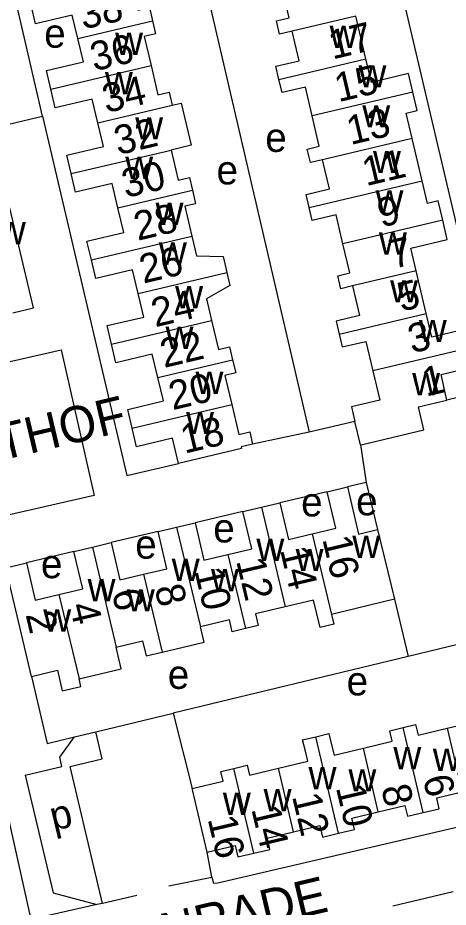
# Model space of a CAD drawing. Extents: x 157646 to 159241, y 379213 to 381217.
# Drawn here: x 158907.8 to 158967.4, y 380734 to 380857.1 of the extents above; entities that cross this region are included whole.
import ezdxf

# ---------------------------------------------------------------- set-up
doc = ezdxf.new("R2010")
doc.units = 0
for name, color, linetype in [('BLT_Basislijn', 7, 'Continuous'), ('BLT_Bebouwing', 7, 'Continuous'), ('BLT_Centroide', 7, 'Continuous'), ('BLT_Huisnummer', 7, 'Continuous'), ('BLT_Huisnummer_ tussenligend', 7, 'Continuous'), ('BLT_Onderverdeling_panden', 7, 'Continuous'), ('BLT_Straatnaam', 7, 'Continuous')]:
    doc.layers.add(name, color=color, linetype=linetype)

msp = doc.modelspace()

# ---------------------------------------------------------------- linework, layer by layer
at = {"layer": 'BLT_Basislijn'}
for p, q in [((158903.89, 380841.72), (158911.21, 380843.45)), ((158973.83, 380805.75), (158967.23, 380804.14)), ((158954.48, 380801.16), (158948.14, 380799.71)), ((158955.27, 380797.94), (158954.48, 380801.16)), ((158948.14, 380799.71), (158940.31, 380798.06)), ((158955.27, 380797.94), (158956.05, 380792.74)), ((158956.05, 380792.74), (158953.46, 380792.12)), ((158950.64, 380791.45), (158944.09, 380789.93)), ((158938.97, 380788.72), (158932.35, 380787.16)), ((158927.22, 380785.95), (158920.74, 380784.41)), ((158915.56, 380783.18), (158908.99, 380781.61)), ((158972.42, 380771.22), (158961.87, 380768.65)), ((158961.87, 380768.65), (158929.32, 380760.8)), ((158909.72, 380765.9), (158911.89, 380756.62)), ((158918.59, 380758.23), (158929.32, 380760.8)), ((158929.32, 380760.8), (158931.95, 380750.4)), ((158911.89, 380756.62), (158915.65, 380757.53)), ((158913.61, 380754.71), (158915.65, 380757.53)), ((158915.65, 380757.53), (158918.59, 380758.23)), ((158919.48, 380754.47), (158918.59, 380758.23)), ((158904.57, 380754.81), (158909.61, 380732.25)), ((158913.92, 380753.43), (158913.61, 380754.71)), ((158915.04, 380753.42), (158919.48, 380754.47)), ((158908.83, 380752.22), (158913.92, 380753.43)), ((158919.54, 380734.49), (158915.04, 380753.42)), ((158908.83, 380752.22), (158912.7, 380735.95)), ((158934.65, 380738.13), (158934.04, 380741.58)), ((158928.73, 380736.91), (158934.65, 380738.13)), ((158912.7, 380735.95), (158918.73, 380734.31)), ((158924.29, 380735.57), (158919.54, 380734.49)), ((158968.1, 380736.07), (158959.72, 380734.11)), ((158918.73, 380734.31), (158909.61, 380732.25)), ((158919.54, 380734.49), (158918.73, 380734.31))]:
    msp.add_line(p, q, dxfattribs=at)
for points in [[(158950.45, 380874.83), (158953.9, 380875.15), (158955.51, 380874.99), (158957.69, 380873.05), (158958.48, 380871.06), (158973.83, 380805.75)], [(158931.91, 380870.58), (158932.87, 380865.39), (158948.14, 380799.71)], [(158911.21, 380843.45), (158907.1, 380861.22), (158906.52, 380864.85)], [(158911.21, 380843.45), (158922.91, 380793.71), (158930.05, 380795.37)], [(158897.4, 380807.37), (158913.83, 380811.08), (158918.39, 380790.92), (158901.96, 380787.2), (158897.4, 380807.37)], [(158956.05, 380792.74), (158957.62, 380786.24)], [(158959.95, 380776.58), (158961.87, 380768.65)], [(158934.65, 380738.13), (158934.9, 380737.3), (158935.48, 380737.32), (158983.21, 380748.46), (158985.53, 380750.59), (158985.91, 380751.64), (158986.02, 380754.38), (158982.31, 380770.52)]]:
    msp.add_lwpolyline(points, dxfattribs=at)
at = {"layer": 'BLT_Bebouwing'}
for p, q in [((158955.99, 380851.35), (158954.6, 380857.26)), ((158963.78, 380834.49), (158962.42, 380840.34)), ((158964.36, 380816.13), (158962.97, 380822.02)), ((158950.64, 380791.45), (158953.46, 380792.12)), ((158938.97, 380788.72), (158941.53, 380789.33)), ((158941.53, 380789.33), (158944.09, 380789.93)), ((158929.79, 380786.55), (158932.35, 380787.16)), ((158927.22, 380785.95), (158929.79, 380786.55)), ((158918.15, 380783.79), (158920.74, 380784.41)), ((158915.56, 380783.18), (158918.15, 380783.79))]:
    msp.add_line(p, q, dxfattribs=at)
for points in [[(158923.49, 380862.09), (158924.44, 380858.1), (158926.04, 380858.48), (158926.47, 380856.64)], [(158945.8, 380855.18), (158944.05, 380854.77), (158943.61, 380856.64), (158945.38, 380857.05), (158944.49, 380860.81)], [(158916.11, 380854.19), (158915.35, 380857.42), (158910.25, 380856.22), (158909.64, 380858.81)], [(158926.47, 380856.64), (158926.89, 380854.85), (158925.3, 380854.47), (158926.25, 380850.44)], [(158943.96, 380848.52), (158943.53, 380850.35), (158946.77, 380851.11), (158945.8, 380855.18)], [(158912.38, 380847.16), (158911.77, 380849.76), (158916.88, 380850.97), (158916.11, 380854.19)], [(158962.48, 380846.77), (158961.88, 380849.32), (158956.76, 380848.11), (158955.99, 380851.35)], [(158926.25, 380850.44), (158927.2, 380846.4), (158928.77, 380846.77), (158929.2, 380844.94)], [(158948.56, 380843.49), (158947.62, 380847.45), (158944.4, 380846.69), (158943.96, 380848.52)], [(158918.89, 380842.5), (158918.12, 380845.78), (158913, 380844.57), (158912.38, 380847.16)], [(158962.42, 380840.34), (158961.59, 380843.87), (158963.08, 380844.22), (158962.48, 380846.77)], [(158929.2, 380844.94), (158930.42, 380845.23), (158931.8, 380839.41), (158929.04, 380838.75)], [(158950, 380837.41), (158948.31, 380837.01), (158947.87, 380838.89), (158949.55, 380839.29), (158948.56, 380843.49)], [(158915.2, 380835.48), (158914.6, 380838.03), (158919.66, 380839.23), (158918.89, 380842.5)], [(158929.04, 380838.75), (158930.02, 380834.59), (158931.57, 380834.96), (158931.99, 380833.18)], [(158948.14, 380830.8), (158947.71, 380832.61), (158950.96, 380833.37), (158950, 380837.41)], [(158921.67, 380830.73), (158920.87, 380834.12), (158915.81, 380832.93), (158915.2, 380835.48)], [(158966.64, 380829.03), (158966.01, 380831.7), (158964.52, 380831.35), (158963.78, 380834.49)], [(158931.99, 380833.18), (158932.43, 380831.32), (158930.91, 380830.97), (158931.89, 380826.83)], [(158907.14, 380816.24), (158909.97, 380816.9), (158906.71, 380830.73)], [(158917.99, 380823.55), (158917.38, 380826.14), (158922.47, 380827.35), (158921.67, 380830.73)], [(158952.81, 380825.77), (158951.87, 380829.77), (158948.57, 380828.99), (158948.14, 380830.8)], [(158962.97, 380822.02), (158962.23, 380825.18), (158967.27, 380826.36), (158966.64, 380829.03)], [(158931.89, 380826.83), (158932.54, 380824.09), (158936.24, 380824.03), (158936.76, 380821.82)], [(158954.16, 380819.94), (158952.53, 380819.56), (158952.1, 380821.36), (158953.76, 380821.75), (158952.81, 380825.77)], [(158924.46, 380818.9), (158923.69, 380822.16), (158918.61, 380820.95), (158917.99, 380823.55)], [(158936.76, 380821.82), (158937.18, 380820.02), (158933.93, 380818.14), (158934.64, 380815.16)], [(158920.8, 380811.88), (158920.19, 380814.45), (158925.24, 380815.64), (158924.46, 380818.9)], [(158954.16, 380819.94), (158955.13, 380815.84), (158951.88, 380815.08), (158952.3, 380813.28)], [(158934.64, 380815.16), (158935.58, 380811.15), (158937.13, 380811.51), (158937.55, 380809.71)], [(158970.81, 380811.46), (158970.2, 380814.05), (158965.13, 380812.86), (158964.36, 380816.13)], [(158952.3, 380813.28), (158952.72, 380811.49), (158955.99, 380812.26), (158956.95, 380808.19)], [(158927.2, 380807.26), (158926.43, 380810.51), (158921.4, 380809.32), (158920.8, 380811.88)], [(158967.23, 380804.14), (158966.4, 380807.68), (158971.42, 380808.86), (158970.81, 380811.46)], [(158937.55, 380809.71), (158937.98, 380807.9), (158936.48, 380807.55), (158937.43, 380803.52)], [(158956.95, 380808.19), (158957.92, 380804.11), (158954.01, 380803.19), (158954.48, 380801.16)], [(158923.64, 380800.26), (158923.02, 380802.85), (158927.96, 380804.02), (158927.2, 380807.26)], [(158955.27, 380797.94), (158955.54, 380798.01), (158964.03, 380800.01), (158963.28, 380803.21), (158967.23, 380804.14)], [(158937.43, 380803.52), (158938.41, 380799.37), (158939.92, 380799.73), (158940.31, 380798.06)], [(158930.05, 380795.37), (158929.23, 380798.85), (158924.25, 380797.68), (158923.64, 380800.26)], [(158940.31, 380798.06), (158938.71, 380797.68), (158938.77, 380797.44), (158930.05, 380795.37)], [(158953.46, 380792.12), (158955, 380785.6), (158957.62, 380786.24)], [(158948.56, 380785.65), (158951.83, 380786.42), (158950.64, 380791.45)], [(158944.09, 380789.93), (158945.29, 380784.87), (158948.56, 380785.65)], [(158936.88, 380782.79), (158940.19, 380783.57), (158938.97, 380788.72)], [(158932.35, 380787.16), (158933.57, 380782.01), (158936.88, 380782.79)], [(158925.2, 380780.04), (158928.44, 380780.81), (158927.22, 380785.95)], [(158957.62, 380786.24), (158959.95, 380776.58)], [(158920.74, 380784.41), (158921.95, 380779.27), (158925.2, 380780.04)], [(158913.5, 380777.22), (158916.79, 380778), (158915.56, 380783.18)], [(158909.72, 380765.9), (158906.16, 380780.93), (158908.99, 380781.61)], [(158908.99, 380781.61), (158910.21, 380776.44), (158913.5, 380777.22)], [(158951.24, 380774.49), (158951.57, 380773.12), (158949.66, 380772.66), (158948.75, 380776.47), (158944.84, 380775.54)], [(158959.95, 380776.58), (158951.24, 380774.49)], [(158944.84, 380775.54), (158940.7, 380774.56), (158941.08, 380772.93), (158939.31, 380772.52)], [(158939.31, 380772.52), (158937.49, 380772.08), (158937.11, 380773.73), (158933.1, 380772.78)], [(158927.79, 380769.25), (158933.6, 380770.62), (158933.1, 380772.78)], [(158921.43, 380769.95), (158925.07, 380770.81), (158925.56, 380768.73), (158927.79, 380769.25)], [(158916.3, 380765.58), (158922.11, 380766.97), (158921.43, 380769.95)], [(158909.72, 380765.9), (158913.28, 380766.75), (158913.96, 380763.88), (158916.52, 380764.49), (158916.3, 380765.58)], [(158967.26, 380758.72), (158971.28, 380759.67), (158970.93, 380761.14), (158972.73, 380761.57)], [(158955.65, 380755.97), (158959.66, 380756.92), (158959.31, 380758.38), (158961.18, 380758.83)], [(158961.18, 380758.83), (158962.89, 380759.23), (158963.24, 380757.77), (158967.26, 380758.72)], [(158943.91, 380753.2), (158947.95, 380754.15), (158947.62, 380755.55), (158947.24, 380757.12), (158949.06, 380757.55)], [(158949.06, 380757.55), (158950.89, 380757.98), (158951.26, 380756.41), (158951.59, 380755.01), (158955.65, 380755.97)], [(158937.71, 380753.17), (158939.55, 380753.6), (158939.87, 380752.24), (158943.91, 380753.2)], [(158931.95, 380750.4), (158936.24, 380751.4), (158935.93, 380752.74), (158937.71, 380753.17)], [(158934.04, 380741.58), (158932.05, 380750), (158931.95, 380750.4)], [(158963.95, 380747.07), (158966.16, 380747.58), (158965.8, 380749.09), (158969.34, 380749.94)], [(158957.72, 380747.15), (158961.4, 380748.02), (158961.75, 380746.55), (158963.95, 380747.07)], [(158952.21, 380744.19), (158954.41, 380744.71), (158954.04, 380746.28), (158957.72, 380747.15)], [(158945.98, 380744.39), (158949.63, 380745.25), (158950.01, 380743.67), (158952.21, 380744.19)], [(158940.47, 380741.44), (158942.7, 380741.96), (158942.33, 380743.53), (158945.98, 380744.39)], [(158934.04, 380741.58), (158937.88, 380742.49), (158938.25, 380740.91), (158940.47, 380741.44)]]:
    msp.add_lwpolyline(points, dxfattribs=at)
at = {"layer": 'BLT_Onderverdeling_panden'}
for p, q in [((158954.6, 380857.26), (158945.8, 380855.18)), ((158916.11, 380854.19), (158926.47, 380856.64)), ((158943.96, 380848.52), (158955.99, 380851.35)), ((158912.38, 380847.16), (158926.25, 380850.44)), ((158962.48, 380846.77), (158948.56, 380843.49)), ((158918.89, 380842.5), (158929.2, 380844.94)), ((158962.42, 380840.34), (158950, 380837.41)), ((158915.2, 380835.48), (158929.04, 380838.75)), ((158948.14, 380830.8), (158963.78, 380834.49)), ((158921.67, 380830.73), (158931.99, 380833.18)), ((158966.64, 380829.03), (158952.81, 380825.77)), ((158917.99, 380823.55), (158931.89, 380826.83)), ((158924.46, 380818.9), (158936.76, 380821.82)), ((158962.97, 380822.02), (158954.16, 380819.94)), ((158920.8, 380811.88), (158934.64, 380815.16)), ((158952.3, 380813.28), (158964.36, 380816.13)), ((158970.81, 380811.46), (158956.95, 380808.19)), ((158927.2, 380807.26), (158937.55, 380809.71)), ((158923.64, 380800.26), (158937.43, 380803.52)), ((158941.53, 380789.33), (158944.84, 380775.54)), ((158929.79, 380786.55), (158933.1, 380772.78)), ((158948.56, 380785.65), (158951.24, 380774.49)), ((158918.15, 380783.79), (158921.43, 380769.95)), ((158936.88, 380782.79), (158939.31, 380772.52)), ((158925.2, 380780.04), (158927.79, 380769.25)), ((158913.5, 380777.22), (158916.3, 380765.58)), ((158963.95, 380747.07), (158961.18, 380758.83)), ((158967.26, 380758.72), (158969.34, 380749.94)), ((158952.21, 380744.19), (158949.06, 380757.55)), ((158957.72, 380747.15), (158955.65, 380755.97)), ((158940.47, 380741.44), (158937.71, 380753.17)), ((158945.98, 380744.39), (158943.91, 380753.2))]:
    msp.add_line(p, q, dxfattribs=at)

# ---------------------------------------------------------------- texts
at = {"layer": 'BLT_Centroide'}
for s, p in [('e', (158911.46, 380852.91)), ('w', (158950.98, 380852.88)), ('w', (158921.28, 380851.91)), ('w', (158919.87, 380846.47)), ('w', (158954.98, 380847.41)), ('w', (158955.5, 380841.88)), ('w', (158924.06, 380840.22)), ('e', (158942.07, 380838.49)), ('w', (158956.98, 380835.56)), ('w', (158922.68, 380834.75)), ('e', (158935.32, 380833.99)), ('w', (158957.34, 380830.12)), ('w', (158926.88, 380828.38)), ('w', (158905.05, 380825.72)), ('w', (158957.8, 380824.28)), ('w', (158927.34, 380822.88)), ('w', (158959.35, 380817.66)), ('w', (158929.59, 380816.84)), ('w', (158963.33, 380812.16)), ('w', (158928.26, 380811.22)), ('w', (158932.41, 380805)), ('w', (158962.41, 380804.81)), ('w', (158931.11, 380799.44)), ('e', (158947.03, 380788.04)), ('e', (158954.65, 380788.19)), ('e', (158934.87, 380784.44)), ('e', (158924.06, 380782.19)), ('w', (158940.84, 380781.88)), ('w', (158954.12, 380782.3)), ('w', (158946.27, 380780.48)), ('e', (158911.01, 380779.49)), ('w', (158929.12, 380779.12)), ('w', (158934.55, 380777.69)), ('w', (158917.47, 380776.31)), ('w', (158922.91, 380774.89)), ('w', (158911.33, 380772.09)), ('e', (158928.57, 380764.17)), ('e', (158953.33, 380763.27)), ('w', (158959.8, 380753.06)), ('w', (158965.27, 380752.81)), ('w', (158948.06, 380750.27)), ('w', (158953.58, 380749.98)), ('w', (158936.2, 380746.73)), ('w', (158941.84, 380747.23))]:
    msp.add_text(s, height=4, dxfattribs=at).set_placement(p)
msp.add_text('p', height=4, rotation=13.3726, dxfattribs=at).set_placement((158912.75, 380744.5))
at = {"layer": 'BLT_Huisnummer'}
for s, rotation, p in [('17', 13.2698, (158951.38, 380851.27)), ('34', 13.3031, (158920.04, 380843.85)), ('13', 13.2698, (158953.87, 380839.43)), ('30', 13.3031, (158922.74, 380832.09)), ('9', 13.2698, (158958.13, 380828.02)), ('26', 13.3031, (158925.17, 380820.25)), ('5', 13.2698, (158960.88, 380816.36)), ('22', 13.3031, (158928.05, 380808.58)), ('1', 13.2698, (158964.32, 380804.61)), ('18', 13.3031, (158930.88, 380796.71)), ('16', 283.3311, (158949.95, 380784.92)), ('10', 283.3311, (158932.24, 380780.54)), ('6', 283.3311, (158920.79, 380777.58)), ('2', 283.3311, (158908.87, 380774.47)), ('6', 283.3299, (158963.86, 380751.83)), ('10', 283.3299, (158951.83, 380750.52)), ('16', 283.3299, (158934.07, 380746.19))]:
    msp.add_text(s, height=4, rotation=rotation, dxfattribs=at).set_placement(p)
at = {"layer": 'BLT_Huisnummer_ tussenligend'}
for s, rotation, p in [('38', 13.3031, (158916.86, 380855.41)), ('36', 13.3031, (158918.37, 380849.63)), ('15', 13.2698, (158952.2, 380845.36)), ('32', 13.3031, (158921.68, 380838.03)), ('11', 13.2698, (158956.02, 380833.74)), ('28', 13.3031, (158924.41, 380826.18)), ('7', 13.2698, (158959.8, 380822.29)), ('24', 13.3031, (158926.82, 380814.21)), ('3', 13.2698, (158962.36, 380810.6)), ('20', 13.3031, (158929.23, 380802.73)), ('14', 283.3311, (158944.1, 380783.43)), ('12', 283.3311, (158938.02, 380781.89)), ('8', 283.3311, (158926.72, 380778.18)), ('4', 283.3311, (158914.95, 380775.7)), ('8', 283.3299, (158958.09, 380750.49)), ('12', 283.3299, (158945.76, 380749.32)), ('14', 283.3299, (158940.12, 380747.55))]:
    msp.add_text(s, height=4, rotation=rotation, dxfattribs=at).set_placement(p)
at = {"layer": 'BLT_Straatnaam'}
for s, rotation, p in [('PUTHOF', 13.3148, (158896.39, 380793.6)), ('IMSTENRADE', 13.3149, (158908.37, 380723.33))]:
    msp.add_text(s, height=5, rotation=rotation, dxfattribs=at).set_placement(p)

doc.saveas('drawing.dxf')
